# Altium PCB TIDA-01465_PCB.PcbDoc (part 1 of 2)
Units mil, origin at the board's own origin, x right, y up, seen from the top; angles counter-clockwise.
Board outline 2770 x 2010 mil, 4 copper layers (Top Layer, MidLayer1, MidLayer2, Bottom Layer), stack 61.2 mil thick; 110 components, 69 nets, 347 pads, 90 vias.
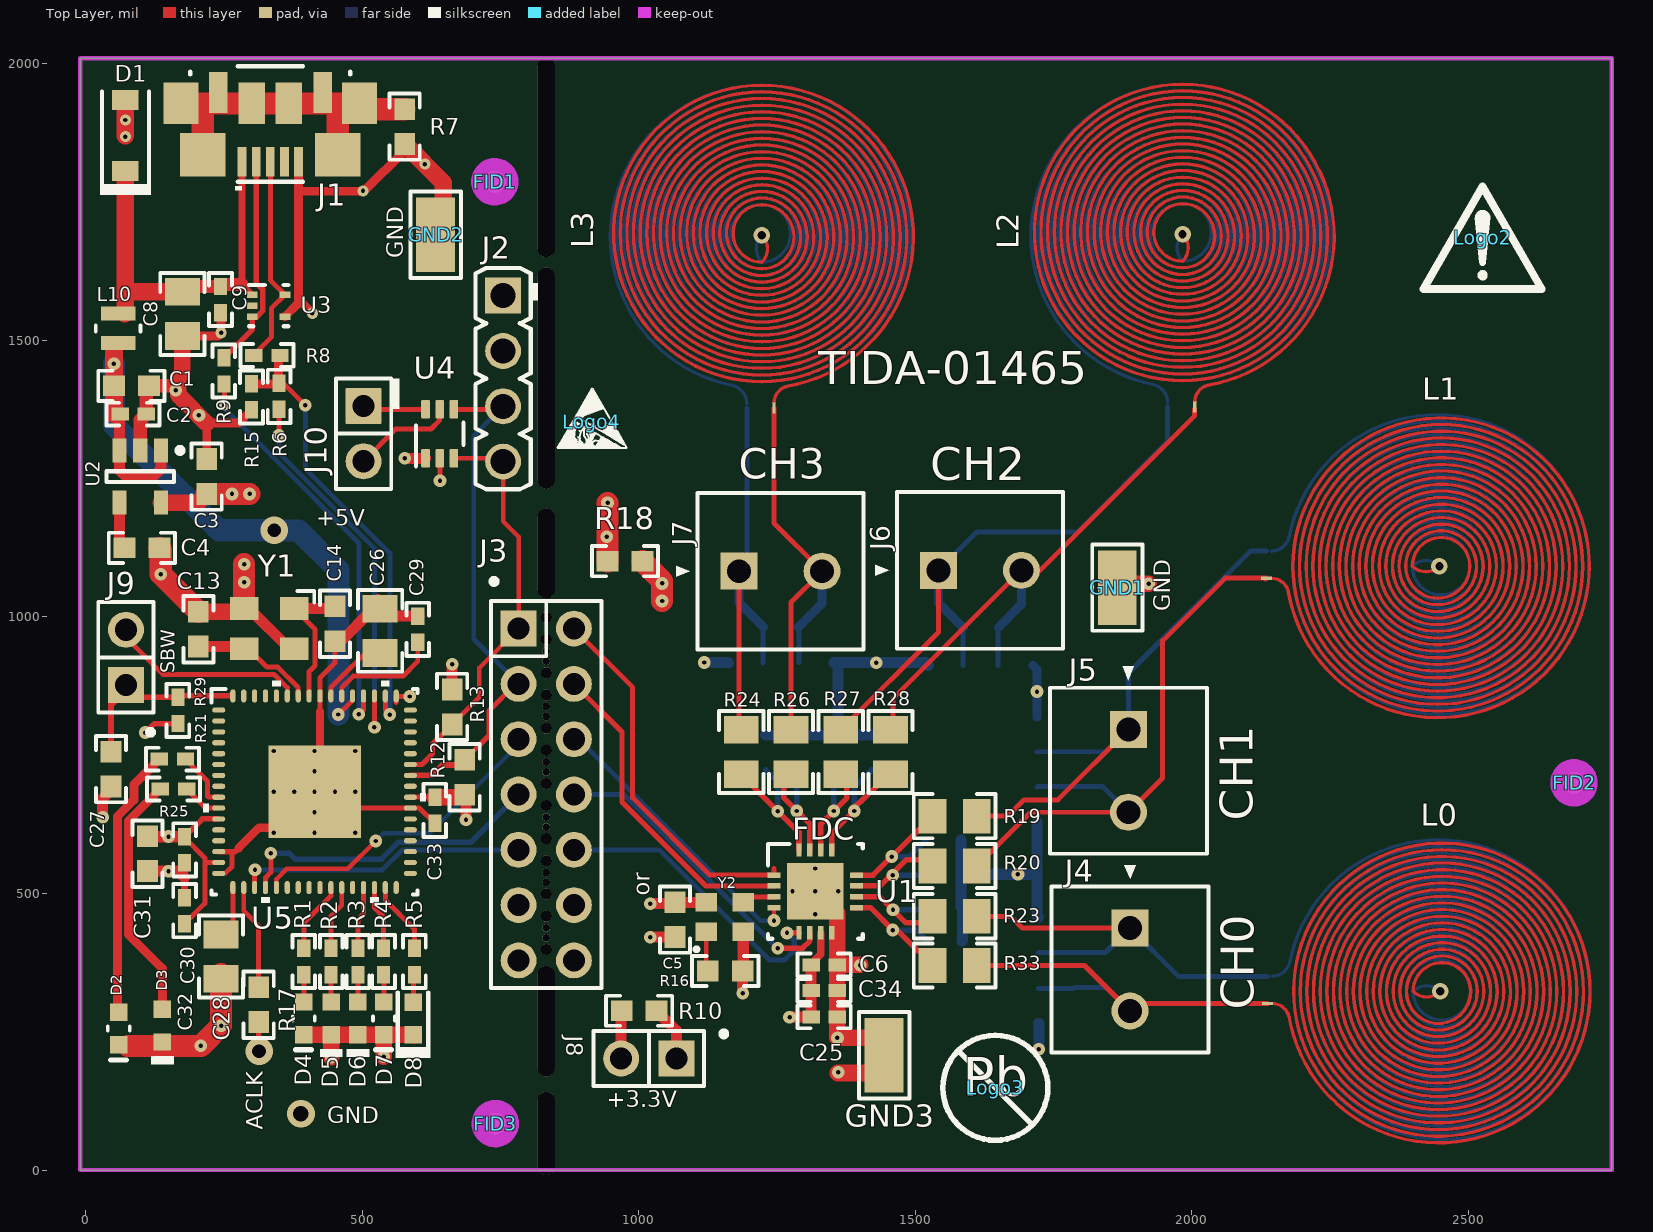
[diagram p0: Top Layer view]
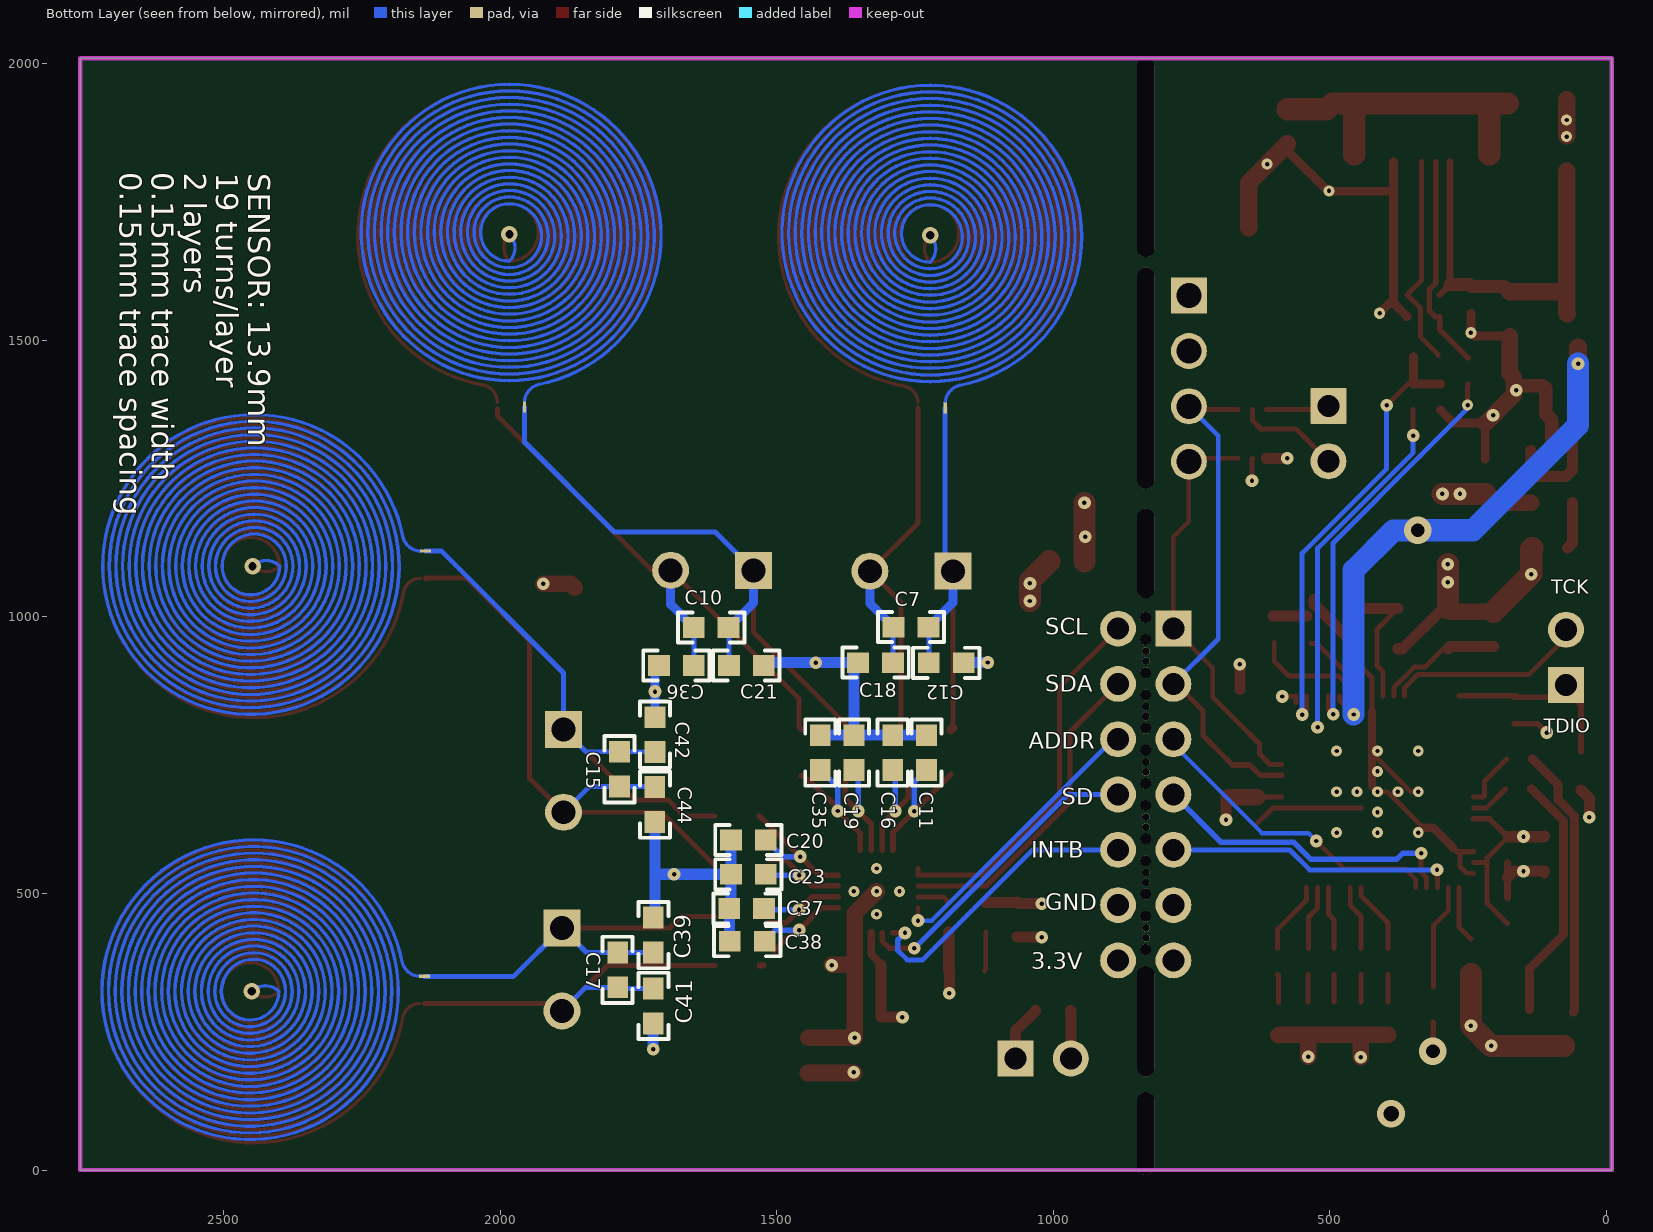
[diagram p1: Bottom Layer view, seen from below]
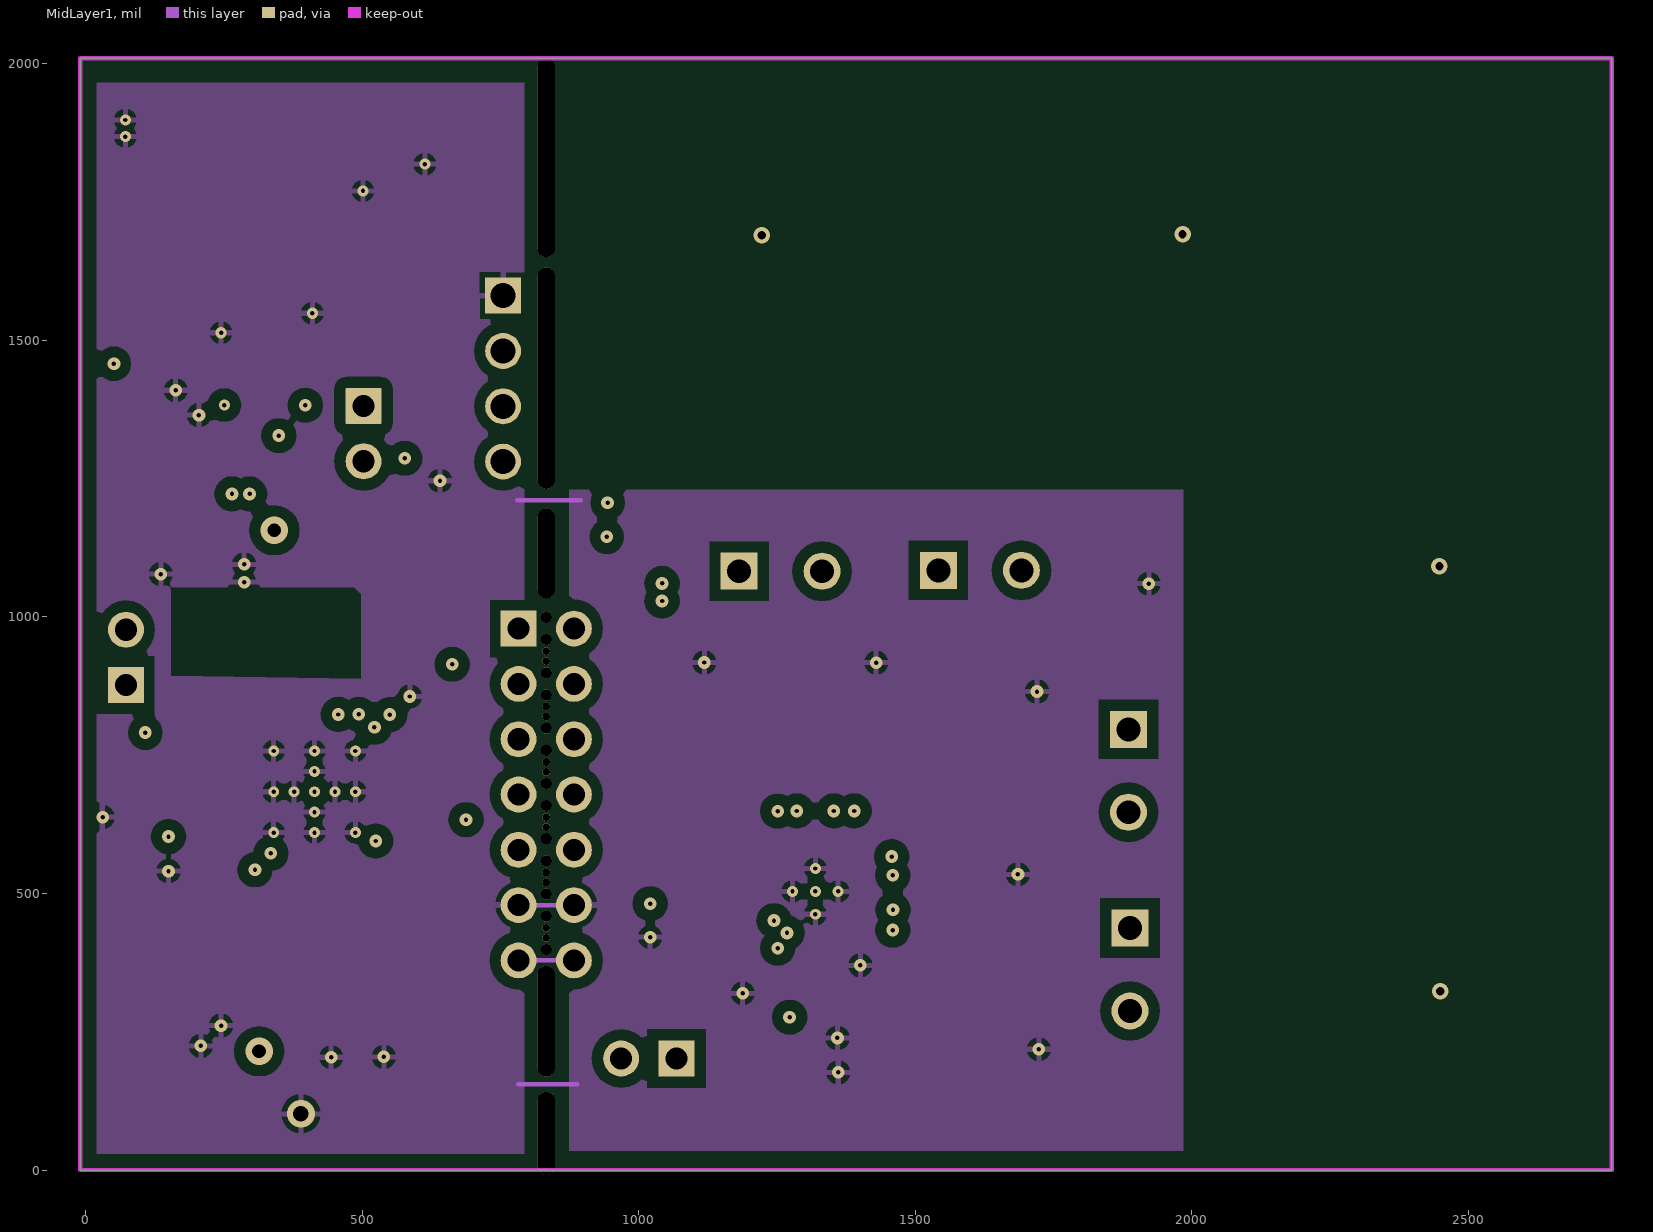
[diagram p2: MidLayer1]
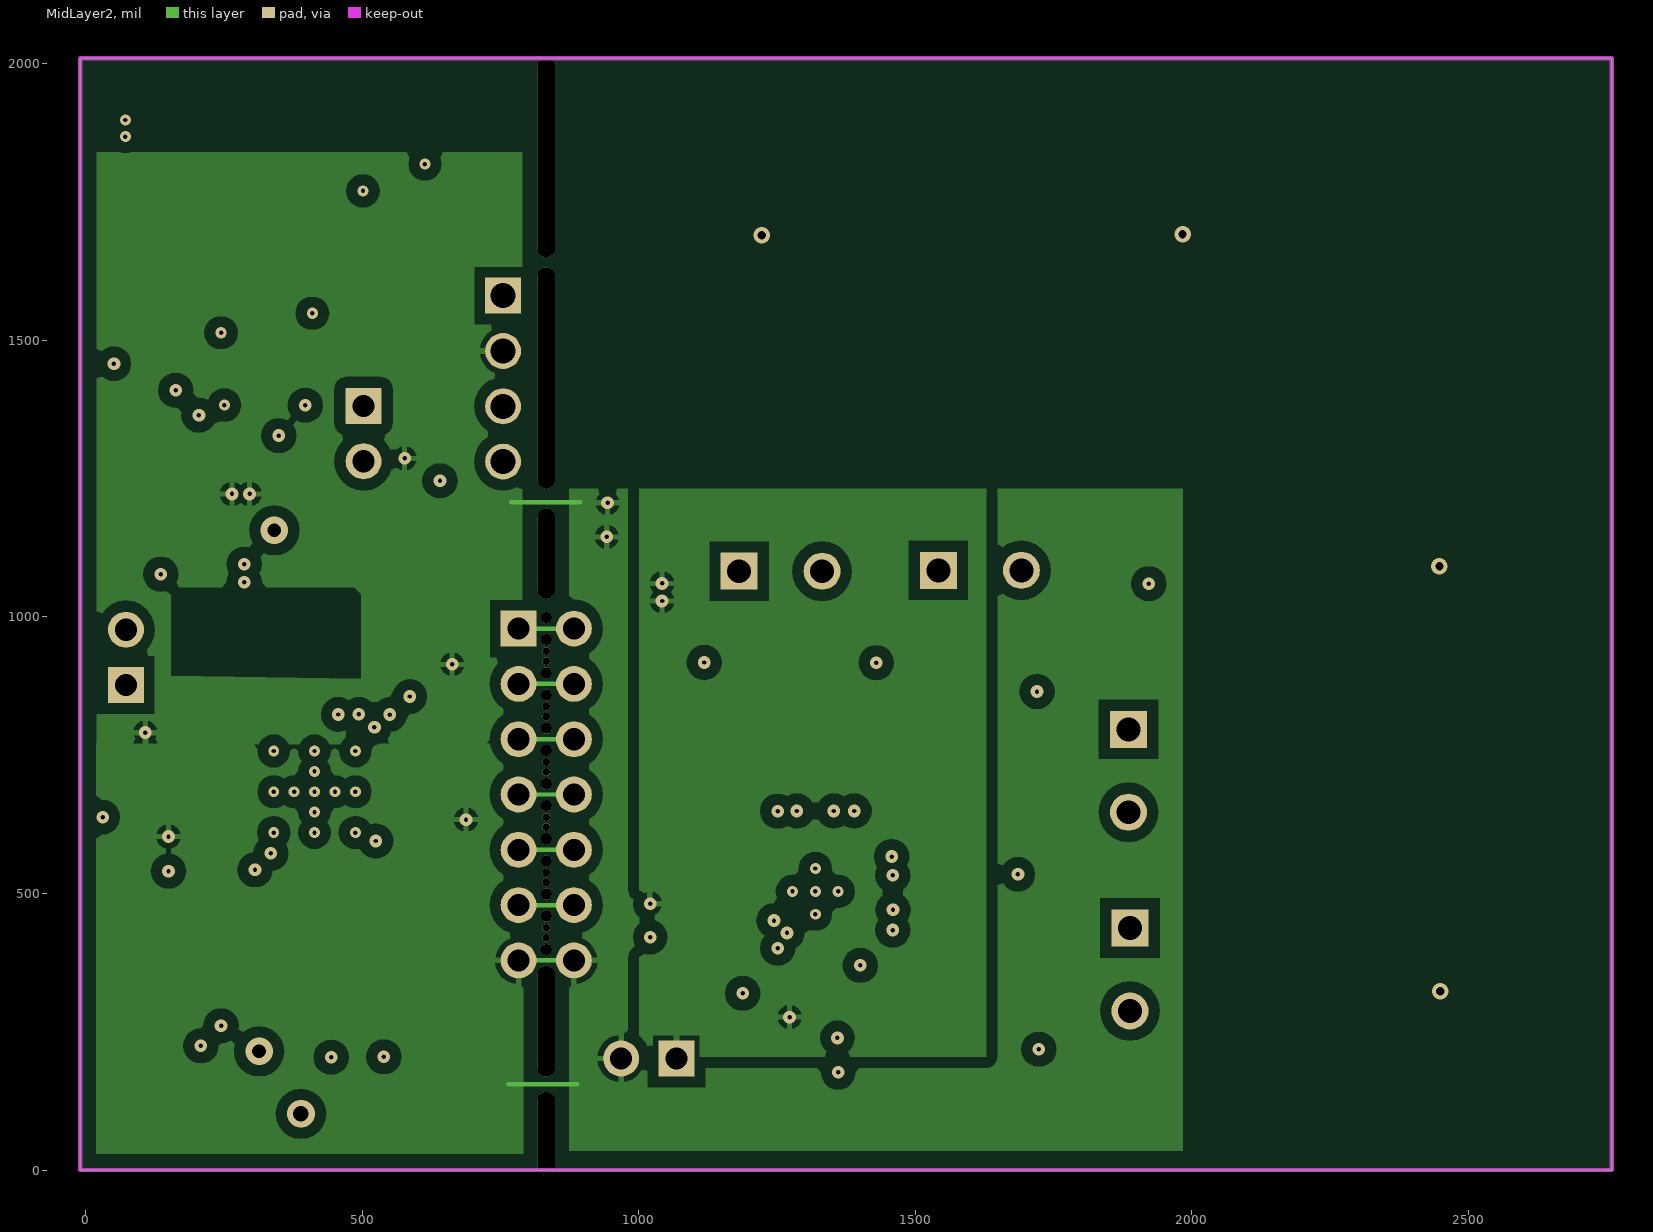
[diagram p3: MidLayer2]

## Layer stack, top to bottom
Top Solder: solder mask 0.4, Solder Resist, Dk 3.5
Top Layer: signal copper 1.4
Dielectric1: core 12.6, FR-4, Dk 3.9
MidLayer1: signal copper 1.4
Dielectric2: prepreg 30.4, FR-4, Dk 3.9
MidLayer2: signal copper 1.4
Dielectric3: core 12.6, FR-4, Dk 4.8
Bottom Layer: signal copper 1.4
Bottom Solder: solder mask 0.4, Solder Resist, Dk 3.5

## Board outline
-10,0 2760,0 2760,2010 -10,2010

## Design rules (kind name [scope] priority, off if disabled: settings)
AcuteAngle [All] p1: minimum=4.50000000000000E+0001 checktracksonly=FALSE
AssemblyTestPointUsage [All] p1: valid=2
Clearance Clearance_BoardEdge_MountingHoles [OnCopper and InComponentClass('Mounting Holes') vs IsKeepOut] p1: gap=40
Clearance Clearance_BoardEdge_Poly [OnCopper and InPoly vs IsKeepOut] p2: gap=25
Clearance Clearance_BoardEdge [OnCopper and Not InComponentClass('Logo') and not InComponentClass('FiducialMark') and not InRegion(1000,500,4000,800) and Not IsKeepout vs IsKeepOut] p3: gap=30
Clearance Clearance_Poly [InPolygon] p4: gap=20
Clearance [All] p5: gap=4
ComponentClearance ComponentClearance_Logo [InComponentClass('Logo')] p1: gap=50 collisioncheckmode=3 verticalgap=10 showdistances=FALSE
ComponentClearance ComponentClearance_ScrewToNut [(HasFootprint('NY PMS 440 0025 PH')) vs (HasFootprint('Keystone_1902C'))] p2: gap=5 collisioncheckmode=3 verticalgap=10 showdistances=FALSE
ComponentClearance ComponentClearance_MountingHoles [InComponentClass('Mounting Holes')] p3: gap=250 collisioncheckmode=3 verticalgap=100000 showdistances=FALSE
ComponentClearance ComponentClearance_SmallPassives [HasFootprint('0201*') or HasFootprint('0402*') or HasFootprint('0508') or HasFootprint('0603*') or HasFootprint('0612') or HasFootprint('0805*') or HasFootprint('0815*') or HasFootprint('0830*') or HasFootprint('1206*') or HasFootprint('1210*') or HasFootprint('1808*') or HasFootprint('1812*') or HasFootprint('1825*') or HasFootprint('2010*') or HasFootprint('2220*') or HasFootprint('2225*') or HasFootprint('2512*') or HasFootprint('2728*') or HasFootprint('3518*') vs HasFootprint('0201*') or HasFootprint('0402*') or HasFootprint('0508') or HasFootprint('0603*') or HasFootprint('0612') or HasFootprint('0805*') or HasFootprint('0815*') or HasFootprint('0830*') or HasFootprint('1206*') or HasFootprint('1210*') or HasFootprint('1808*') or HasFootprint('1812*') or HasFootprint('1825*') or HasFootprint('2010*') or HasFootprint('2220*') or HasFootprint('2225*') or HasFootprint('2512*') or HasFootprint('2728*') or HasFootprint('3518*')] p4: gap=20 collisioncheckmode=3 verticalgap=10 showdistances=FALSE
ComponentClearance ComponentClearance_THtoSMT [IsThruComponent vs IsSMTComponent] p5: gap=75 collisioncheckmode=3 verticalgap=30 showdistances=FALSE
ComponentClearance ComponentClearance_THtoTH [IsThruComponent vs IsThruComponent] p6: gap=78.74 collisioncheckmode=3 verticalgap=30 showdistances=TRUE
ComponentClearance [All] p7: gap=40 collisioncheckmode=3 verticalgap=10 showdistances=FALSE
DiffPairsRouting [All] p1: maxlimit=100 minlimit=10 mostfreqgap=10 toplayer_minwidth=15 toplayer_maxwidth=15 toplayer_prefwidth=15 midlayer1_minwidth=15 midlayer1_maxwidth=15 midlayer1_prefwidth=15 midlayer2_minwidth=15 midlayer2_maxwidth=15 midlayer2_prefwidth=15 bottomlayer_minwidth=15 bottomlayer_maxwidth=15 bottomlayer_prefwidth=15 maxuncoupledlength=1000
FabricationTestPointUsage TestPointUsage [All] p1: valid=2 allowmultiple=FALSE
FabricationTestpoint Testpoint [All] p1: side=3 testpointundercomponent=TRUE minsize=40 maxsize=100 preferedsize=60 minholesize=0 maxholesize=40 preferedholesize=32 testpointgrid=1 allowsidetop=TRUE allowsidebottom=TRUE usegrid=TRUE gridtolerance=0.01
FanoutControl Fanout_LCC [IsLCC] p1: bgadir=Out bgaviamode=Centered fanoutstyle=Auto fanoutdirection=Alternating viagrid=1 // Fanout_LCC (Default Rule)
FanoutControl Fanout_BGA [IsBGA] p2: bgadir=Out bgaviamode=Centered fanoutstyle=Auto fanoutdirection=Alternating viagrid=1 // Fanout_BGA (Default Rule)
FanoutControl Fanout_Default [All] p4: bgadir=Out bgaviamode=Centered fanoutstyle=Auto fanoutdirection=Alternating viagrid=1 // Fanout_Default (Default Rule)
FanoutControl Fanout_Small [(CompPinCount < 5)] p5: bgadir=Out bgaviamode=Centered fanoutstyle=Auto fanoutdirection=OutThenIn viagrid=1 // Fanout_Small (Default Rule)
HoleSize [All] p1: absolutevalues=TRUE maxlimit=251 minlimit=7.87 maxpercent=80.000 minpercent=20.000
HoleToHoleClearance [All] p1: gap=21 allowstackedmicrovias=TRUE
MinimumAnnularRing MinimumAnnularRing_ThermalPadVias [IsVia and InAnyComponent] p1: minimumring=5.91
MinimumAnnularRing [All] p2: minimumring=6
MinimumSolderMaskSliver MinimumSolderMaskSliver_Logo [InComponentClass('Logo') vs InComponentClass('Logo')] p1: minsoldermaskwidth=0.7
MinimumSolderMaskSliver [All] p2: minsoldermaskwidth=3.94
PlaneConnect [All] p1: planeconnectstyle=Relief reliefexpansion=10 reliefentries=4 reliefconductorwidth=10 reliefairgap=10
PolygonConnect [All] p1: connectstyle=Relief reliefconductorwidth=10 reliefentries=4 polygonreliefangle="90 Angle" airgapwidth=10
RoutingVias ThermalPadVias [IsVia and InAnyComponent] p1: holewidth=7.87 width=19.68 viastyle="Through Hole" minholewidth=7.87 minwidth=19.68 maxholewidth=12.99 maxwidth=23.62
RoutingVias [All] p2: holewidth=16 width=34 viastyle="Through Hole" minholewidth=7.87 minwidth=20 maxholewidth=40 maxwidth=65
SMDToCorner [All] p1: distance=30000
SilkToSilkClearance [All] p1: silktosilkclearance=5
SilkToSolderMaskClearance SilkscreenOverComponentPads [IsPad] p1: minsilkscreentomaskgap=5 clearancetoexposedcopper=TRUE
SolderMaskExpansion [All] p1: expansion=1.97
Width [All] p1: maxlimit=100 minlimit=4 preferedwidth=10 checkconnectedcopper=TRUE
15 further rules are at their usual default settings.

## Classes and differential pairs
component class FiducialMark: FID1 FID2 FID3
component class BlankSheet: !PCB C1 C2 C3 C4 C5 C6 C7 C8 C9 C10 C11 C12 C13 C14 C15 C16 C17 C18 C19 C20 C21 C23 C25 C26 C27 C28 C29 C30 C31 C32 C33 C34 C35 C36 C37 C38 C39 C41 C42 C44 D1 D2 D3 D4 D5 D6 D7 D8 GND1 GND2 GND3 J1 J2 J3 J6 J7 J8 J9 J10 L0 L1 L2 L3 L10 R1 R2 R3 R4 R5 R6 R7 R8 R9 R10 R12 R13 R15 R16 R17 R18 R19 R20 R21 R23 R24 R25 R26 R27 R28 R29 R33 U1 U2 U3 U4 U5 Y1 Y2
component class Header: J2 J3 J8 J9 J10
component class AssemblyNote: ZZ1 ZZ2 ZZ3 ZZ4
component class EVM_Hardware: !PCB FID1 FID2 FID3 LBL1 Logo1 Logo2 Logo3 Logo4 ZZ1 ZZ2 ZZ3 ZZ4

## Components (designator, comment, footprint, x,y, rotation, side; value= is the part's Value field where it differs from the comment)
C1 "C1608X5R1A106M" 0603 83,1418 r0 top
C2 "GRM155R71C104JA88D" 0402 85.99,1366.82 r0 top
C3 "C0603C225K8PACTU" 0603 219,1254 r90 top
C4 "C1608C0G1E103J" 0603 102,1125 r0 top
C5 "C1608C0G1E103J" 0603 1065.83,452.78 r270 top
C6 "C1005X7R1C103K" 0402 1335.55,370.84 r0 top
C7 "06035A390JAT2A" 0603 1257.48,981.73 r180 bottom
C8 "C2012X5R1C226K125AC" 0805_HV 175,1548 r270 top
C9 "GRM155R71C104JA88D" 0402 244,1574 r270 top
C10 "06035A390JAT2A" 0603 1618.8,980.91 r180 bottom
C11 "GRM1885C2A180JA01D" 0603 1229.55,754.84 r270 bottom
C12 "GRM1885C2A180JA01D" 0603 1193.74,917.19 r0 bottom
C13 "GRM1885C2A180JA01D" 0603 204,978 r270 top
C14 "GRM1885C2A180JA01D" 0603 450.96,987.77 r90 top
C15 "06035A390JAT2A" 0603 1784.46,724.84 r90 bottom
C16 "GRM1885C2A180JA01D" 0603 1290.55,754.84 r90 bottom
C17 "06035A390JAT2A" 0603 1788,361.86 r90 bottom
C18 "GRM1885C2A180JA01D" 0603 1321.59,917.53 r0 bottom
C19 "GRM1885C2A180JA01D" 0603 1360.55,754.84 r270 bottom
C20 "GRM1885C2A180JA01D" 0603 1551.55,596.84 r180 bottom
C21 "GRM1885C2A180JA01D" 0603 1555.21,912.33 r0 bottom
C23 "GRM1885C2A180JA01D" 0603 1551.55,534.84 r0 bottom
C25 "GRM155R61A105KE15D" 0402 1335.55,276.84 r0 top
C26 "08053C224JAT2A" 0805_HV 532.52,974.89 r90 top
C27 "C0603X222K5RACTU" 0603 46,725 r90 top
C28 "08053C224JAT2A" 0805_HV 245,386 r270 top
C29 "C1005C0G1H221F050BA" 0402 600.64,977.76 r90 top
C30 "GRM155R71C104JA88D" 0402 179,579 r270 top
C31 "C1608X5R1A106M" 0603 112,572 r270 top
C32 "GRM155R71C104JA88D" 0402 179,469 r90 top
C33 "GRM155R71C104JA88D" 0402 631.54,650.38 r270 top
C34 "GRM155R71C104JA88D" 0402 1335.55,324.84 r0 top
C35 "GRM1885C2A180JA01D" 0603 1421.55,754.84 r90 bottom
C36 "GRM1885C2A180JA01D" 0603 1681.7,912.33 r0 bottom
C37 "GRM1885C2A180JA01D" 0603 1554.55,472.84 r180 bottom
C38 "GRM1885C2A180JA01D" 0603 1553.55,413.84 r0 bottom
C39 "GRM1885C2A180JA01D" 0603 1723.36,424.9 r270 bottom
C41 "GRM1885C2A180JA01D" 0603 1723.36,296.7 r270 bottom
C42 "GRM1885C2A180JA01D" 0603 1720.36,787.35 r270 bottom
C44 "GRM1885C2A180JA01D" 0603 1720.61,660.88 r270 bottom
D1 "MMSZ5232B-7-F" SOD-123 72,1870.73 r90 top
D2 "LG L29K-G2J1-24-Z" "LG L29K_GREEN" 60,256 r270 top
D3 "SML-LX0603SRW-TR" SML-LX0603SRW_SuperRed 139,261 r270 top
D4 "LG L29K-G2J1-24-Z" "LG L29K_GREEN" 394.55,274.29 r270 top
D5 "SML-LX0603SRW-TR" SML-LX0603SRW_SuperRed 444.16,274.29 r270 top
D6 "SML-LX0603SRW-TR" SML-LX0603SRW_SuperRed 492.53,274.29 r270 top
D7 "LG L29K-G2J1-24-Z" "LG L29K_GREEN" 539.4,274.29 r270 top
D8 "19-21UYC/S530-A4/TR8" 19-21_Yellow 592.18,273.89 r90 top
FID1 "Fiducial" Fiducial10-20 740,1787 r0 top
FID2 "Fiducial" Fiducial10-20 2691.42,700.19 r0 top
FID3 "Fiducial" Fiducial10-20 741,84 r0 top
GND1 "5015" Testpoint_Keystone_Miniature 1865.41,1053.14 r90 top
GND2 "5015" Testpoint_Keystone_Miniature 632.83,1691.26 r90 top
GND3 "5015" Testpoint_Keystone_Miniature 1443.7,207.66 r90 top
J1 "ZX62R-B-5P" Hirose_ZX62R-B-5P 334,1928.73 r90 top
J2 "61300411121" WURTH_61300411121 755,1431 r270 top
J3 "TSW-107-07-G-D" TSW-107-07-G-D 833,679 r270 top
J4 "1727010" PhoenixConact_1727010 1888.57,362.57 r270 top (schematic designator J7)
J5 "1727010" PhoenixConact_1727010 1885.73,721.96 r270 top (schematic designator J6)
J6 "1727010" PhoenixConact_1727010 1617.14,1084.42 r0 top (schematic designator J5)
J7 "1727010" PhoenixConact_1727010 1256.83,1082.75 r0 top (schematic designator J4)
J8 "TSW-102-07-G-S" TSW-102-07-G-S#1 1018.5,201.68 r180 top
J9 "TSW-102-07-G-S" TSW-102-07-G-S#1 73,927 r90 top
J10 "TSW-102-07-G-S" TSW-102-07-G-S#2 502.74,1331.55 r270 top
L0 "PRINTED COIL" PCBComponent_1 2448.79,322.4 r270 top (schematic designator L4)
L1 "PRINTED COIL" PCBComponent_1 2447.46,1091.26 r270 top (schematic designator L3)
L2 "PRINTED COIL" PCBComponent_1 1984.34,1691.7 r0 top
L3 "PRINTED COIL" PCBComponent_1 1223.54,1689.89 r0 top (schematic designator L1)
L10 "VLS201610ET-100M" VLS201610ET 59,1522 r270 top
Logo2 "CAUTION.  READ USER GUIDE BEFORE USE" IEC_Caution_Small 2526.15,1685.99 r0 top
Logo3 "Pb-Free Symbol" Pb-Free_Overlay_Medium 1645.01,148.71 r0 top
Logo4 "ESD Susceptible" ESD_Overlay_Small 915.24,1353.12 r0 top
R1 "CRCW04021K00JNED" 0402 394.55,377.06 r90 top
R2 "CRCW04021K00JNED" 0402 444.16,377.06 r90 top
R3 "CRCW04021K00JNED" 0402 492.53,377.06 r90 top
R4 "CRCW04021K00JNED" 0402 538.87,377.06 r90 top
R5 "CRCW04021K00JNED" 0402 594.56,377.06 r90 top
R6 "CRCW04021K50JNED" 0402 350,1399 r270 top
R7 "CRCW060333R0JNEA" 0603 577,1886.73 r90 top
R8 "CRCW040210R0FKED" 0402 328,1473 r0 top
R9 "CRCW040210R0FKED" 0402 250,1445 r270 top
R10 "CRCW06030000Z0EA" 0603 1000.88,287.98 r0 top
R12 "RC0603FR-074K7L" 0603 685.49,710.26 r90 top
R13 "RC0603FR-074K7L" 0603 662.89,837.32 r270 top
R15 "RC0402JR-071ML" 0402 300,1398 r90 top
R16 "CRCW06030000Z0EA" 0603 1156.65,359.81 r180 top
R17 "CRCW060333R0JNEA" 0603 313,299 r270 top
R18 "CRCW06030000Z0EA" 0603 975.41,1100.89 r0 top
R19 "CRCW08050000Z0EA" 0805_HV 1571.55,639.84 r0 top
R20 "CRCW08050000Z0EA" 0805_HV 1571.55,549.84 r0 top
R21 "CRCW04021K00JNED" 0402 157,743 r180 top
R23 "CRCW08050000Z0EA" 0805_HV 1571.55,458.84 r0 top
R24 "CRCW08050000Z0EA" 0805_HV 1185.55,755.84 r90 top
R25 "CRCW04021K00JNED" 0402 159,689 r180 top
R26 "CRCW08050000Z0EA" 0805_HV 1275.55,755.84 r90 top
R27 "CRCW08050000Z0EA" 0805_HV 1365.55,755.84 r90 top
R28 "CRCW08050000Z0EA" 0805_HV 1455.55,755.84 r90 top
R29 "CRCW040233K0JNED" 0402 167,831 r90 top
R33 "CRCW08050000Z0EA" 0805_HV 1571.55,369.84 r0 top
U1 "FDC2114RGHR" RGH0016A 1319.55,503.84 r0 top
U2 "LP2985AIM5-3.3/NOPB" MF05A_N 99,1254 r270 top
U3 "TPD2E001DRLR" DRL0005A 331,1563 r0 top
U4 "TPL0401C-50DCKR" DCK0006A_N 640.39,1331.34 r90 top
U5 "MSP430F5528IRGC" RGC0064B 414,684 r0 top
Y1 "ABM8-24.000MHZ-B2-T" XTAL_ABM8 332,979 r270 top
Y2 "625L3C040M00000" OSC_CTS_625 1155.71,457.21 r90 top
ZZ1 "This Assembly Note is for PCB labels only" AssemblyNoteLabel 3369,1115 r90 top
ZZ2 "These assemblies are ESD sensitive, ESD precautions shall be observed." AssemblyNote 3192,6014 r90 top
ZZ3 "These assemblies must be clean and free from flux and all contaminants. Use of no clean flux is not acceptable." AssemblyNote 3015,6014 r90 top
ZZ4 "These assemblies must comply with workmanship standards IPC-A-610 Class 2, unless otherwise specified." AssemblyNote 2837,6014 r90 top

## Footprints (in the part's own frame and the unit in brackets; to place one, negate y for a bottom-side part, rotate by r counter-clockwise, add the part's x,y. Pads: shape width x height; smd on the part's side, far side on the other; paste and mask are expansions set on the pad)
19-21_Yellow [mm] "SMD, 2-Leads, Body 0.8x1.6mm, Pin Spacing 1.5mm"
  rect 0.8x0.8 smd: 1(-0.75,0) 2(0.75,0)
  silkscreen extent -1.8,-0.8 1.2,0.8, body extent -0.9,-0.45 0.9,0.45, height 1.01
0402 [mm] "0402 from SM-752 data"
  rect 0.8x0.6 smd: 1(-0.6,0) 2(0.6,0)
  silkscreen extent -1.22,-0.52 1.22,0.52, body extent -0.55,-0.3 0.55,0.3, height 0.6
0603 [mm] "0603 from SM-752 data"
  rect 1x0.95 smd: 1(-0.8,0) 2(0.8,0)
  silkscreen extent -1.52,-0.69 1.52,0.69, body extent -0.87,-0.47 0.87,0.47, height 0.85
0805_HV [mil] "0805 with 30mil clearance between pads"
  rect 50x63 smd: 1(-40,0) 2(40,0)
  silkscreen extent -74,-40 74,40, body extent -43,-29 43,29, height 43
AssemblyNote [mil] "Assembly Note"
AssemblyNoteLabel [mil] "Assembly Note for PCB Labels"
DCK0006A_N [mm] "SOT23, 6-Leads, Body 2x1.3mm, Pitch 0.65mm, Lead Span 2.1mm, IPC Medium Density"
  rrect25% 0.85x0.4 smd: 1(-1.125,0.65) 2(-1.125,0) 3(-1.125,-0.65) 4(1.125,-0.65) 5(1.125,0) 6(1.125,0.65)
  silkscreen extent -1.5,-1.09 0.51,1.09, body extent -1.14,-1 1.14,1, height 0.95
DRL0005A [mm] "SOTFL, 5-Flat Leads, Body 1.2x1.6x0.6mm, Pitch 0.5mm, TI recommended"
  rect 0.5x0.3 smd: 1(-0.75,0.5) 2(-0.75,0) 3(-0.75,-0.5) 4(0.75,-0.5) 5(0.75,0.5)
  silkscreen extent -0.9,-0.95 0.9,0.95, body extent -0.85,-0.85 0.85,0.85, height 0.62
ESD_Overlay_Small [mil]
  silkscreen extent -62,-48 64,61
Fiducial10-20 [mm]
  round 1 smd mask+0.5: 1(0,0)
  Top Layer keep-out circle w1.178: c0,0 r0.5
Hirose_ZX62R-B-5P [mm] "Hirose"
  rect 1.35x0.4 smd: 1(-2.68,1.3) 2(-2.68,0.65) 3(-2.68,0) 4(-2.68,-0.65) 5(-2.68,-1.3)
  rect 2x2.1 smd: 6(-2.35,-3.1) 7(-2.35,3.1)
  rect 1.9x1.6 smd: 8(0,-4.1) 13(0,4.1)
  rect 1.88x0.85 smd: 9(0.495,-2.4) 12(0.495,2.4)
  rect 1.9x1.2 smd: 10(0,-0.85) 11(0,0.85)
  silkscreen extent -4,-3.67 1.7,3.67, body extent -2.57,-3.48 2.11,3.45, height 2.65
IEC_Caution_Small [mil]
  silkscreen extent -107,-93 107,92
"LG L29K_GREEN" [mm] "OSRAM"
  rect 0.8x0.8 smd paste-0.4: 1(-0.75,0) 2(0.75,0)
  silkscreen extent -0.1,-0.5 1.45,0.5, body extent -0.9,-0.45 0.9,0.45, height 0.67
MF05A_N [mm] "SOT23, 5-Leads, Body 2.9x1.6mm, Pitch 0.95mm, Lead Span 2.8mm, IPC Medium Density"
  rect 1.1x0.65 smd: 1(-1.2,0.95) 2(-1.2,0) 3(-1.2,-0.95) 4(1.2,-0.95) 5(1.2,0.95)
  silkscreen extent -1.32,-1.55 0.25,1.95, body extent -0.9,-1.55 0.9,1.55, height 1.19
OSC_CTS_625 [mm] "CTS"
  rect 0.85x1 smd: 1(-0.675,0.85) 2(-0.675,-0.85) 3(0.675,-0.85) 4(0.675,0.85)
  silkscreen extent -1.52,1.25 -1.43,1.35, body extent -1.1,-1.35 1.1,1.35, height 1.02
Pb-Free_Overlay_Medium [mil]
  silkscreen extent -95,-95 95,95
PCBComponent_1 [mil]
  rect 6x19.68 smd: 1(21.13,-311.93)
  rect 6x19.68 smd far side: 2(-27.93,-311.85)
  Top Layer lines w6: 21.13,-303.1 cw(c53.47,-303.72) 44.83,-272.55 ccw(c-0.7,-2.36) -0.7,271.64 ccw(c-0.7,3.64) -0.7,-264.36 ccw(c-0.7,-2.36) -0.7,259.64 ccw(c-0.7,3.64) -0.7,-252.36 ccw(c-0.7,-2.36) -0.7,247.64 ccw(c-0.7,3.64) -0.7,-240.36 ccw(c-0.7,-2.36) -0.7,235.64 ccw(c-0.7,3.64) -0.7,-228.36 ccw(c-0.7,-2.36) -0.7,223.64 ccw(c-0.7,3.64) -0.7,-216.36 ccw(c-0.7,-2.36) -0.7,211.64 ccw(c-0.7,3.64) -0.7,-204.36 ccw(c-0.7,-2.36) -0.7,199.64 ccw(c-0.7,3.64) -0.7,-192.36 ccw(c-0.7,-2.36) -0.7,187.64 ccw(c-0.7,3.64) -0.7,-180.36 ccw(c-0.7,-2.36) -0.7,175.64 ccw(c-0.7,3.64) -0.7,-168.36 ccw(c-0.7,-2.36) -0.7,163.64 ccw(c-0.7,3.64) -0.7,-156.36 ccw(c-0.7,-2.36) -0.7,151.64 ccw(c-0.7,3.64) -0.7,-144.36 ccw(c-0.7,-2.36) -0.7,139.64 ccw(c-0.7,3.64) -0.7,-132.36 ccw(c-0.7,-2.36) -0.7,127.64 ccw(c-0.7,3.64) -0.7,-120.36 ccw(c-0.7,-2.36) -0.7,115.64 ccw(c-0.7,3.64) -0.7,-108.36 ccw(c-0.7,-2.36) -0.7,103.64 ccw(c-0.7,3.64) -0.7,-96.36 ccw(c-0.7,-2.36) -0.7,91.64 ccw(c-0.7,3.64) -0.7,-84.36 ccw(c-0.7,-2.36) -0.7,79.64 ccw(c-0.7,3.64) -0.7,-72.36 ccw(c-0.7,-2.36) -0.7,67.64 ccw(c-0.7,3.64) -0.7,-60.36 ccw(c-0.7,-2.36) -0.7,55.64 ccw(c-0.7,3.64) -0.7,-48.36 ccw(c-25.2,-23.86) -0.7,0.64
  Bottom Layer lines w6: -27.9,-303.16 ccw(c-61.61,-303.99) -54.25,-271.08 cw(c-0.7,-2.36) -0.7,271.64 cw(c-0.7,3.64) -0.7,-264.36 cw(c-0.7,-2.36) -0.7,259.64 cw(c-0.7,3.64) -0.7,-252.36 cw(c-0.7,-2.36) -0.7,247.64 cw(c-0.7,3.64) -0.7,-240.36 cw(c-0.7,-2.36) -0.7,235.64 cw(c-0.7,3.64) -0.7,-228.36 cw(c-0.7,-2.36) -0.7,223.64 cw(c-0.7,3.64) -0.7,-216.36 cw(c-0.7,-2.36) -0.7,211.64 cw(c-0.7,3.64) -0.7,-204.36 cw(c-0.7,-2.36) -0.7,199.64 cw(c-0.7,3.64) -0.7,-192.36 cw(c-0.7,-2.36) -0.7,187.64 cw(c-0.7,3.64) -0.7,-180.36 cw(c-0.7,-2.36) -0.7,175.64 cw(c-0.7,3.64) -0.7,-168.36 cw(c-0.7,-2.36) -0.7,163.64 cw(c-0.7,3.64) -0.7,-156.36 cw(c-0.7,-2.36) -0.7,151.64 cw(c-0.7,3.64) -0.7,-144.36 cw(c-0.7,-2.36) -0.7,139.64 cw(c-0.7,3.64) -0.7,-132.36 cw(c-0.7,-2.36) -0.7,127.64 cw(c-0.7,3.64) -0.7,-120.36 cw(c-0.7,-2.36) -0.7,115.64 cw(c-0.7,3.64) -0.7,-108.36 cw(c-0.7,-2.36) -0.7,103.64 cw(c-0.7,3.64) -0.7,-96.36 cw(c-0.7,-2.36) -0.7,91.64 cw(c-0.7,3.64) -0.7,-84.36 cw(c-0.7,-2.36) -0.7,79.64 cw(c-0.7,3.64) -0.7,-72.36 cw(c-0.7,-2.36) -0.7,67.64 cw(c-0.7,3.64) -0.7,-60.36 cw(c-0.7,-2.36) -0.7,55.64 cw(c-0.7,3.64) -0.7,-48.36 cw(c23.8,-23.86) -0.7,0.64
  Multi-Layer pour cut-out: -373.7,5 -345.25,-138.07 -264.2,-259.36 -142.91,-340.4 0.15,-368.86 0.15,-368.86 143.22,-340.4 264.51,-259.36 345.55,-138.07 374.01,5 374.01,5 345.56,148.07 264.51,269.36 143.23,350.4 0.16,378.86 0.16,378.86 -142.91,350.4 -264.2,269.36 -345.25,148.07 -373.7,5
PhoenixConact_1727010 [mm]
  rect 1.7x1.7 hole 1.1: 1(-1.905,0)
  round 1.7 hole 1.1: 2(1.905,0)
  silkscreen extent -4.8,-3.6 3.81,3.6, body extent -3.81,-3.6 3.81,3.7, height 8.52
RGC0064B [mm]
  oval 0.6x0.24 smd mask+0.07: 1(-4.4,3.75) 2(-4.4,3.25) 3(-4.4,2.75) 4(-4.4,2.25) 5(-4.4,1.75) 6(-4.4,1.25) 7(-4.4,0.75) 8(-4.4,0.25) 9(-4.4,-0.25) 10(-4.4,-0.75) 11(-4.4,-1.25) 12(-4.4,-1.75) 13(-4.4,-2.25) 14(-4.4,-2.75) 15(-4.4,-3.25) 16(-4.4,-3.75) 33(4.4,-3.75) 34(4.4,-3.25) 35(4.4,-2.75) 36(4.4,-2.25) 37(4.4,-1.75) 38(4.4,-1.25) 39(4.4,-0.75) 40(4.4,-0.25) 41(4.4,0.25) 42(4.4,0.75) 43(4.4,1.25) 44(4.4,1.75) 45(4.4,2.25) 46(4.4,2.75) 47(4.4,3.25) 48(4.4,3.75)
  oval 0.24x0.6 smd mask+0.07: 17(-3.751,-4.4) 18(-3.251,-4.4) 19(-2.751,-4.4) 20(-2.251,-4.4) 21(-1.75,-4.4) 22(-1.25,-4.4) 23(-0.75,-4.4) 24(-0.25,-4.4) 25(0.25,-4.4) 26(0.75,-4.4) 27(1.25,-4.4) 28(1.75,-4.4) 29(2.251,-4.4) 30(2.751,-4.4) 31(3.251,-4.4) 32(3.751,-4.4) 49(3.751,4.4) 50(3.251,4.4) 51(2.751,4.4) 52(2.251,4.4) 53(1.75,4.4) 54(1.25,4.4) 55(0.75,4.4) 56(0.25,4.4) 57(-0.25,4.4) 58(-0.75,4.4) 59(-1.25,4.4) 60(-1.75,4.4) 61(-2.251,4.4) 62(-2.751,4.4) 63(-3.251,4.4) 64(-3.751,4.4)
  rect 4.25x4.25 smd paste-2.112: 65(0,0)
  silkscreen extent -5.1,-5.1 5.1,5.1, body extent -4.57,-4.57 4.57,4.57, height 1.01
RGH0016A [mm] "QFN, 16-Leads, Body 4x4mm, Pitch 0.5mm, TI Recommended"
  rect 0.6x0.25 smd: 1(-1.9,0.75) 2(-1.9,0.25) 3(-1.9,-0.25) 4(-1.9,-0.75) 9(1.9,-0.75) 10(1.9,-0.25) 11(1.9,0.25) 12(1.9,0.75)
  rect 0.25x0.6 smd: 5(-0.75,-1.9) 6(-0.25,-1.9) 7(0.25,-1.9) 8(0.75,-1.9) 13(0.75,1.9) 14(0.25,1.9) 15(-0.25,1.9) 16(-0.75,1.9)
  rect 2.6x2.6 smd paste-1.3: 17(0,0)
  silkscreen extent -2.17,-2.17 2.17,2.17, body extent -2.05,-2.05 2.05,2.05, height 0.81
SML-LX0603SRW_SuperRed [mm] "Lumex Opto/Components Inc"
  rect 0.8x0.8 smd: 1(-0.75,0) 2(0.75,0)
  silkscreen extent 1.4,-0.53 1.78,0.52, body extent -0.92,-0.53 0.92,0.53, height 1.1
SOD-123 [mm] "On Semi recommended land pattern"
  rect 0.915x1.22 smd: 1(-1.637,0) 2(1.637,0)
  silkscreen extent -2.74,-1.17 2.03,1.17, body extent -1.93,-0.9 1.93,0.9, height 1.35
Testpoint_Keystone_Miniature [mil] "Miniature SMT test point"
  rect 135x70 smd: 1(0,0)
  silkscreen extent -78,-46 78,45, body extent -52,-20 52,20, height 61
TSW-102-07-G-S#1 [mm] "Samtec 100mil, 1x2, 230 mil above insulator"
  rect 1.65x1.65 hole 1.016 mask+0: 1(-1.27,0)
  round 1.65 hole 1.016 mask+0: 2(1.27,0)
  silkscreen extent -3.57,-1.27 2.54,1.27, body extent -2.54,-1.27 2.54,1.27, height 8.38
TSW-102-07-G-S#2 [mm] "Samtec 100mil, 1x2, 230 mil above insulator"
  rrect6% 1.65x1.65 hole 1.016: 1(-1.27,0)
  round 1.65 hole 1.016: 2(1.27,0)
  silkscreen extent -2.54,-1.27 2.54,1.65, body extent -2.54,-1.27 2.54,1.27, height 8.38
TSW-107-07-G-D [mm] "Samtec 100mil, 2x7, 230 mil above insulator"
  rect 1.65x1.65 hole 1.016 mask+0: 1(-7.62,-1.27)
  round 1.65 hole 1.016 mask+0: 2(-7.62,1.27) 3(-5.08,-1.27) 4(-5.08,1.27) 5(-2.54,-1.27) 6(-2.54,1.27) 7(0,-1.27) 8(0,1.27) 9(2.54,-1.27) 10(2.54,1.27) 11(5.08,-1.27) 12(5.08,1.27) 13(7.62,-1.27) 14(7.62,1.27)
  silkscreen extent -9.91,-2.54 8.89,2.54, body extent -8.89,-2.54 8.89,2.54, height 8.38
VLS201610ET [mm] "TDK"
  rect 0.65x1.6 smd: 1(-0.675,0) 2(0.675,0)
  silkscreen extent -0.15,-1.02 0.15,1.02, body extent -1.05,-0.85 1.05,0.85, height 0.95
WURTH_61300411121 [mm] "Header, 2.54mm, 4x1, TH"
  rect 1.65x1.65 hole 1.15: 1(-3.81,0)
  round 1.65 hole 1.15: 2(-1.27,0) 3(1.27,0) 4(3.81,0)
  silkscreen extent -5.08,-1.27 5.08,1.6, body extent -5.08,-1.27 5.08,1.27, height 8.54
XTAL_ABM8 [mm] "Abracon recommended land pattern"
  rect 1.05x1.3 smd: 1(-0.925,1.15) 2(-0.925,-1.15) 3(0.925,-1.15) 4(0.925,1.15)
  silkscreen extent -1.73,1.3 -1.2,2.07, body extent -1.35,-1.7 1.35,1.7, height 0.8

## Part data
C1 C31: "CAP, CERM, 10uF, 10V, +/-20%, X5R, 0603"
C2 C9 C30 C32 C33 C34: library part 0402YC132KAT2A, "CAP CER 0.1UF 16V 5% X7R 0402"
C3: "CAP, CERM, 2.2uF, 10V, +/-10%, X5R, 0603"
C4 C5: "CAP, CERM, 0.01uF, 25V, +/-5%, C0G/NP0, 0603"
C6: "CAP, CERM, 0.01 μF, 16 V, +/- 10%, X7R, 0402"
C7 C10 C15 C17: "CAP, CERM, 39 pF, 50 V, +/- 5%, C0G/NP0, 0603"
C8: "CAP, CERM, 22uF, 16V, +/-10%, X5R, 0805"
C11 C12 C13 C14 C16 C18 C19 C20 C21 C23 C35 C36 C37 C38 C39 C41 C42 C44: "CAP, CERM, 18pF, 100V, +/-5%, C0G/NP0, 0603"
C25: "CAP, CERM, 1uF, 10V, +/-10%, X5R, 0402"
C26 C28: "CAP, CERM, 0.22 μF, 25 V, +/- 5%, X7R, 0805"
C27: "CAP, CERM, 2200pF, 50V, +/-10%, X7R, 0603"
C29: library part 0402YC132KAT2A, "CAP CER 220PF 50V 1% NP0 0402"
D1: "Diode, Zener, 5.6V, 500mW, SOD-123"
D2 D4 D7: "LED, Green, SMD"
D3 D5 D6: "LED, Super Red, SMD"
D8: "LED, Yellow, SMD"
FID1 FID2 FID3: "Fiducial mark.  There is nothing to buy or mount."
GND1 GND2 GND3: "Test Point, Miniature, SMT"
J1: "Connector, Receptacle, Micro-USB Type B, SMT"
J2: "Header, 2.54 mm, 4x1, Gold, TH"
J3: "Header, 100mil, 7x2, Gold, TH"
J4 J5 J6 J7: "Conn Term Block, 2POS, 3.81mm, TH"
J8 J9 J10: "Header, TH, 100mil, 2x1, Gold plated, 230 mil above insulator"
L0 L1 L2 L3: "8.2MM 2-layer Coil 3.5uH"
L10: "Inductor, Shielded, Ferrite, 10 μH, 0.4 A, 1.38 ohm, SMD"
Logo2: library part IEC_Caution, "IEC 61010-1 Caution Warning"
Logo3: library part Pb-Free
Logo4: library part ESD_Susceptible, "ESD Susceptible Symbol"
R1 R2 R3 R4 R5 R21 R25: "RES, 1.0k ohm, 5%, 0.063W, 0402"
R6: library part CRCW040233K0JNED, "RES 1.5K OHM 1/16W 5% 0402 SMD"
R7 R17: "RES, 33 ohm, 5%, 0.1W, 0603"
R8 R9: "RES, 10.0, 1%, 0.063 W, 0402"
R10 R16 R18: "RES, 0 ohm, 5%, 0.1W, 0603"
R12 R13: "RES, 4.70k ohm, 1%, 0.1W, 0603"
R15: library part CRCW040233K0JNED, "RES,1M ohm, 5%, 0.063W, 0402"
R19 R20 R23 R24 R26 R27 R28 R33: "RES, 0 ohm, 5%, 0.125W, 0805"
R29: "RES, 33k ohm, 5%, 0.063W, 0402"
U1: "Multi-Channel 12/26-Bit Capacitance to Digital Converter (FDC) for Capacitive Sensing, RGH0016A"
U2: "Micropower 150 mA Low-Noise Ultra Low-Dropout Regulator, 5-pin SOT-23, Pb-Free"
U3: "Low-Capacitance + / - 15 kV ESD-Protection Array for High-Speed Data Interfaces, 2 Channels, -40 to +85 degC, 5-pin SOT (DRL), Green (RoHS & no Sb/Br)"
U4: "128 TAPS Single Channel Digital Potentiometer with I2C Interface, DCK0006A (SOT-6)"
U5: "Mixed Signal MicroController, RGC0064B"
Y1: "Crystal, 24.000MHz, 18pF, SMD"
Y2: "OSC, 40 MHz, 3.3 V, SMD"
ZZ1: library part AssemblyNoteLabel
ZZ2 ZZ3 ZZ4: library part AssemblyNote

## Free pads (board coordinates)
  oval 31x150 hole 31 slot 150 at 90 deg unplated: 0(832.98,66.07)
  oval 31x200 hole 31 slot 200 at 90 deg unplated: 0(832.98,269)
  oval 31x162 hole 31 slot 162 at 90 deg unplated: 0(832.98,1114.98)
  oval 31x400 hole 31 slot 400 at 90 deg unplated: 0(832.98,1432.1)
  oval 31x360 hole 31 slot 360 at 90 deg unplated: 0(832.98,1830.72)
  round 20 hole 20 unplated: 0(833,399) 0(833,459) 0(833,499) 0(833,559) 0(833,599) 0(833,659) 0(833,699) 0(833,759) 0(833,799) 0(833,859) 0(833,899) 0(833,959) 0(833,999)
  round 14 hole 14 unplated: 0(833,420) 0(833,438) 0(833,520) 0(833,538) 0(833,620) 0(833,638) 0(833,720) 0(833,738) 0(833,820) 0(833,838) 0(833,920) 0(833,938)

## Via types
v1: diameter 23, hole 8, Top Layer to Bottom Layer, tented both sides, 58 vias
v2: diameter 19.68, hole 7.87, Top Layer to Bottom Layer, 18 vias
v3: diameter 20, hole 8, Top Layer to Bottom Layer, tented both sides, 7 vias
v4: diameter 30, hole 15, Top Layer to Bottom Layer, tented both sides, 4 vias
v5: diameter 50, hole 25, Top Layer to Bottom Layer, 2 vias
v6: diameter 50, hole 28, Top Layer to Bottom Layer, 1 vias

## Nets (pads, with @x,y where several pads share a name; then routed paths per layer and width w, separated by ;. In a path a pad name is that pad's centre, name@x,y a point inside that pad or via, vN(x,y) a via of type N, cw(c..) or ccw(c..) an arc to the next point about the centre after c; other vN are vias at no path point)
+3.3V: C3.1 C30.1 C31.1 C32.1 C33.1 J2.2 J3.13 J3.14 J8.2 R10.1 R12.1 R13.1 R18.1 R29.1 U2.5 U4.1 U5.11 U5.15 U5.40 | length 1466
  Top Layer w9: C30.1@178.19,601.81 215.79,564.21 215.79,482.17 C32.1@179,445.38 C32.1@179,446.38 ; 218.51,556.05 U5.15@240.77,556.05 ; U5.40@587.23,674.16 631.38,674.16 C33.1@631.54,674 ; R12.1@680.72,674 R12.1@685.49,678.76
  Top Layer w10: v1(108,791) 124.38,807.38 R29.1@167,807.38 ; C30.1@179,602.62 211.17,634.79 U5.11@240.77,634.79
  Top Layer w20: C31.1@112,603.5 112.87,602.62 C30.1@177.38,602.62 ; v1(576.96,1286.9) 614.66,1286.9 U4.1@614.8,1287.05 ; R13.1@662.89,868.81 v1@662.89,914.41 ; R12.1@685.49,678.76 687.96,676.29 v1(687.96,633.52) ; J8.2@968.5,201.68 968.5,287.1 R10.1@969.38,287.98
  Top Layer w30: U2.5@136.4,1206.76 203.25,1206.76 C3.1@219,1222.5 ; C33.1@631.54,674 R12.1@680.72,674
  Top Layer w40: C3.1@219,1222.5 v1(296.5,1222.5) ; R18.1@943.91,1100.89 v1(943.91,1206.39)
  MidLayer1 w8: J3.13@793,379 J3.14@883,379 J3.14@893,379
  MidLayer2 w8: 764,155 889,155 ; 769.81,1207.11 894.81,1207.11 ; J3.13@773,379 J3.13@783,379 J3.14@883,379
  other v1: 150,603 662.95,914.48 942.41,1144.89 264.73,1222.5
+5V: C1.1 C2.1 L10.2 U2.1 U2.3 U5.53 | length 1259.2
  Top Layer w9: v1(457.05,823.75) 482.91,849.62 U5.53@482.91,857.23
  Top Layer w20: C2.1@62.36,1366.82 61.6,1366.05 U2.3@61.6,1301.24 61.6,1265.79 73.39,1254 122.32,1254 136.4,1268.08 U2.1@136.4,1301.24
  Top Layer w32: C2.1@51.5,1366.82 C1.1@51.5,1418 L10.2@51.5,1487.93
  Bottom Layer w40: 51.23,1346.77 v1(51.23,1457.93) ; 60,1338 241.18,1156.82 v5(341.31,1156.82) 385.14,1156.53 457.05,1084.62 v1(457.05,823.75)
ADDR: J3.5 J3.6 U1.4 U5.21 | length 1184.6
  Top Layer w8: U5.21@345.09,510.77 345.09,525.97 363.69,544.57 474.18,544.57 v1(524.58,594.98) ; U1.4@1244.74,474.31 1244.85,474.21 v1(1244.85,451.03)
  MidLayer2 w8: J3.5@783,779 J3.6@883,779
  Bottom Layer w8: v1(524.58,594.98) 538.92,609.31 622.89,609.31 783,769.42 J3.5@783,779 ; J3.6@883,779 891.97,779 1219.95,451.03 v1(1244.85,451.03)
CLKIN: U1.3 Y2.3 | length 60.4
  Top Layer w9: Y2.3@1189.18,483.78 1199.4,494 U1.3@1244.74,494 U1.3@1244.33,493.59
